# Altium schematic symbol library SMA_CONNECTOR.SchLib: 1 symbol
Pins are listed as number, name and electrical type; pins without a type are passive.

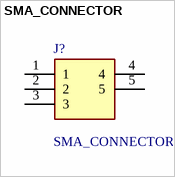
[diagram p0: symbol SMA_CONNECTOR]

## SMA_CONNECTOR
designator J?
LPRS - SMA CONNECTOR - CONNECTOR, SMA, ANTENNA; Geometry.Height: 8.3mm
footprint SMACONNECTOR
pins: 1, 2, 3, 4, 5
